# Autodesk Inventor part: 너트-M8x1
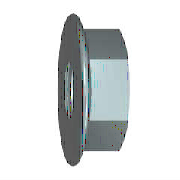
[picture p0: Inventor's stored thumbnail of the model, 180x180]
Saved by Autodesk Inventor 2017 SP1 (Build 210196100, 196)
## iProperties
Created: 2015-12
Part Number: 너트-M8x1
Material: 스테인리스강
Description: 플랜지붙이 6각 너트 - 일반 스레드
Document SubType Name: Modeling
Standard: ISO 4161
Designer: mdu
Standard Revision: 2판 1999-03-15
Standards Organization: ISO
Language: ko-KR
Size Designation: M8
Categories: <MemberInstance><Categories><Category DisplayName="조임쇠" InternalName="e4da775c-781d-43d5-af7c-5136215cf5a6" Mnemonic="FSTN"><Category DisplayName="너트" InternalN
Density: 8.08 g/cm^3
Appearance: 강철
Mass: 9.03298 g
Surface Area: 8.90186 cm^2
Volume: 1.11794 cm^3
Author: mdu
IsCustomPart: 1
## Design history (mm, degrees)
sketch "스케치1"
  geometry: L1 (-1.844, 0)-(9.641, 0) reference; L2 (3.107, 6.5)-(2.288, 8.257); L3 (3.107, 6.5)-(8, 6.5); L4 (8, 6.5)-(8, 0); L5 (3.107, 6.5)-(3.107, 0); L6 (0, -1.835)-(0, 11.01) reference; A1 r 1.2 centre (1.2, 7.75) between (2.288, 8.257) and (0, 7.75); 1 further point
  constraints: 8 end point, 3 point on line, 2 perpendicular, 2 point on circle, 2 tangent, 1 centre point, 1 parallel
  dimensions: "d2" = 13 diameter of L3 L1 (= SW); "d4" = 17.9 dimension on A1 L1 (= LADI); "d5" = 1.2 radius of A1 (= PHH); "d15" = 8 distance between parallel lines of L4 L6 (= KOH); "d16" = 25 deg angle of L6 L2 (= KEWI)
revolve "링" sketch "스케치1" stored, may be unused: angle "d8" = 90 deg
sketch "스케치2"
  geometry: L1 (-6.5, -3.753)-(-6.5, 3.753); L2 (-6.5, 3.753)-(0, 7.506); L3 (0, 7.506)-(6.5, 3.753); L4 (6.5, 3.753)-(6.5, -3.753); L5 (6.5, -3.753)-(0, -7.506); L6 (0, -7.506)-(-6.5, -3.753); C1 r 4.9 at (0, 0); C2 r 7.75 at (0, 0) reference; 1 further point
  constraints: 12 end point, 1 centre point, 1 coincident, 1 vertical, 11 other
  dimensions: "d6" = 15.01111 distance of L5.end L2.end (= 1.1547 x SW)
extrude "본체" join sketch "스케치2" distance "d7" = 8 (= KOH); taper "d9" = 0 deg
sketch "스케치3"
  geometry: L1 (2.638, 7.506)-(8, 7.506) reference; L2 (8, 3.753)-(8, 7.506) reference; L3 (0, -7.75)-(0, 7.75) reference; L4 (-1.6, 0)-(9.6, 0) reference; L5 (7.419, 7.506)-(8, 6.5)
  constraints: 2 end point, 2 point on line
  dimensions: "d10" = 30 deg angle of L2 L5 (= ANG1); "d11" = 13 diameter of L5.end L4 (= SW0)
revolve "모따기1" sketch "스케치3" stored, may be unused: angle "d24" = 90 deg
sketch "스케치4"
  geometry: C1 r 7.75 at (0, 0) reference; 1 further point
  constraints: 1 coincident
hole "스레드" sketch "스케치4" at (0, 0) diameter "d25" = 6.647; stored, may be unused: countersink angle "d29" = 82 deg, drill point angle "d31" = 118 deg; dims "d26" = 6, "d27" = 4, "d28" = 2, "d30" = 8
workaxis "Work Axis1"
workplane "Work Plane1"
body "Solid1"
chamfer "모따기2" distance "d12" = 0.67658 (= -0.5 x GD1 + 0.5 x NND); stored, may be unused: angle "d13" = 30 deg, second distance "d46" = 0.67658 (= -0.5 x GD1 + 0.5 x NND)
chamfer "모따기3" distance "d51" = 0.67658 (= -0.5 x GD1 + 0.5 x NND); stored, may be unused: second distance "d52" = 2, angle "d53" = 45 deg
other parameters: "ANG1" = 30 deg [user parameter; used in 1 equation term], "KEWI" = 25 deg [user parameter; used in 1 equation term], "NND" = 8 [user parameter; used in 4 equation terms], "LADI" = 17.9 [user parameter; used in 2 equation terms], "SW" = 13 [user parameter; used in 3 equation terms], "PHH" = 1.2 [user parameter; used in 3 equation terms], "KOH" = 8 (= NND) [user parameter; used in 2 equation terms], "SW0" = 13 [user parameter; used in 1 equation term], "GD1" = 6.64684 (computed from THREADDIA, PTC, TOA) [user parameter; used in 3 equation terms], "d1" = 17.9 (= LADI), "d3" = 1.2 (= PHH), "d45" = 0, "d47" = 0, "d49" = 0, "d54" = 0, "GUL" = 0.67658 (= 0.541266 x PTC) [user parameter], "TPU" = 8 (computed from PTC) [user parameter], "RR" = 1.2 (= PHH) [user parameter], "THREADDIA" = 8 [user parameter; used in 1 equation term], "TOA" = 30 deg [user parameter; used in 1 equation term], "PTC" = 1.25 [user parameter; used in 4 equation terms], "GAL" = 0.67658 (= 0.541266 x PTC) [user parameter], "E0" = 15.015 (= 1.155 x SW) [user parameter]
